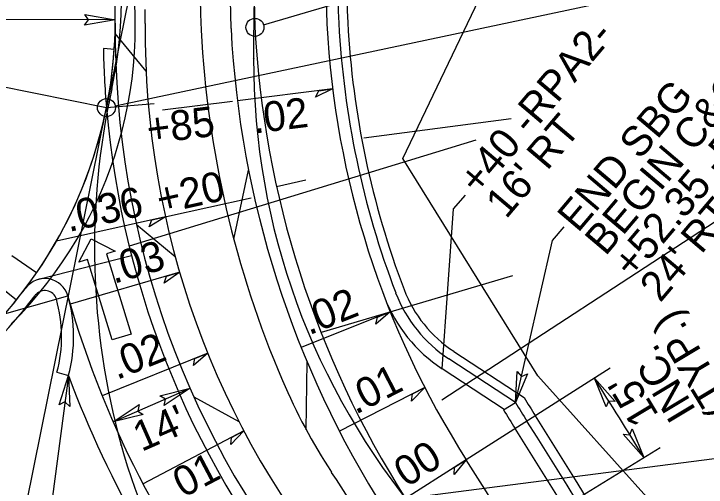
# Model space of a CAD drawing. Extents: x 1761082 to 1764358, y 421907 to 425434.
# Drawn here: x 1762765.1 to 1762880.6, y 423538.8 to 423617.8 of the extents above; entities that cross this region are included whole.
import ezdxf

# ---------------------------------------------------------------- set-up
doc = ezdxf.new("R2010")
doc.units = 0
for name, color, linetype in [('MARK HOOKS CENTER STRAIGHT LEFT TURN ARROW CELL', 7, 'Continuous'), ('MARK LEFT TURN ARROW CELL', 7, 'Continuous'), ('MARK STRAIGHT RIGHT ARROW CELL', 7, 'Continuous'), ('MARK UTURN ARROW CELL', 7, 'Continuous'), ('Prop Conc Shoulder Berm Gutter', 7, 'Continuous'), ('Prop Geotechnical Rock Plating', 7, 'Continuous'), ('Prop Horizontal Alignment Tick Large', 7, 'Continuous'), ('Prop Mkg 3ft Min Skp 3ft Wide White', 7, 'Continuous'), ('Prop Mkg 3ft Min Skp 9ft Wide White', 7, 'Continuous'), ('Prop Mkg Min Skp 6ft Yellow', 7, 'Continuous'), ('Prop Mkg Skp Wht', 7, 'Continuous'), ('Prop Mkg Solid White Diagonals', 7, 'Continuous'), ('Prop Mkg Solid White Edge Line', 7, 'Continuous'), ('Prop Mkg Solid White Lane Line', 7, 'Continuous'), ('Prop Mkg Solid White Multiple Diagonals V8i', 7, 'Continuous'), ('Prop Mkg Solid White Stop Bar', 7, 'Continuous'), ('Prop Mkg Solid White Wide Lane Line', 7, 'Continuous'), ('Prop Mkg Solid Yel Skip LT', 7, 'Continuous'), ('Prop Mkg Solid Yel Skip RT', 7, 'Continuous'), ('Prop Mkg Solid Yellow Diagonals', 7, 'Continuous'), ('Prop Mkg Solid Yellow Edge Line', 7, 'Continuous'), ('Prop Mkg Solid Yellow Lane Line', 7, 'Continuous'), ('Prop Mkr Yel 80ft Spc', 7, 'Continuous'), ('Scratch_Level_0', 7, 'Continuous'), ('Scratch_Level_1', 7, 'Continuous'), ('Scratch_Level_5', 7, 'Continuous')]:
    doc.layers.add(name, color=color, linetype=linetype)

msp = doc.modelspace()

# ---------------------------------------------------------------- linework, layer by layer
at = {"layer": 'MARK HOOKS CENTER STRAIGHT LEFT TURN ARROW CELL'}
for p, q in [((1762808.94, 423589.01), (1762813.82, 423590.09)), ((1762768.94, 423574.59), (1762764.82, 423577.42))]:
    msp.add_line(p, q, dxfattribs=at)
at = {"layer": 'MARK LEFT TURN ARROW CELL'}
for p, q in [((1762848.79, 423552.93), (1762837.68, 423560.24)), ((1762772.33, 423558), (1762774.26, 423557.48))]:
    msp.add_line(p, q, dxfattribs=at)
for centre, radius, start, end in [((1762902.22, 423620.56), 83, 139.7301, 182.9577), ((1762967.14, 423623.91), 148, 182.9577, 200.8339), ((1762707.06, 423616.97), 77, 302.5921, 323.1892), ((1762770.31, 423569.64), 2, 15.7844, 143.1892), ((1762850.31, 423579.46), 23, 200.8339, 236.6832), ((1762750.11, 423563.93), 23, 345.065, 15.7844)]:
    msp.add_arc(centre, radius, start, end, dxfattribs=at)
at = {"layer": 'MARK STRAIGHT RIGHT ARROW CELL'}
for centre, radius, start, end in [((1763313.22, 423228.23), 700, 137.52342, 147.0162), ((1762902.22, 423620.56), 97, 139.7301, 182.9577), ((1762967.14, 423623.91), 162, 182.9577, 212.4627)]:
    msp.add_arc(centre, radius, start, end, dxfattribs=at)
at = {"layer": 'MARK UTURN ARROW CELL'}
for points in [[(1762806.79, 423615.98), (1762960.53, 423661.22), (1763043.33, 423758.96)], [(1762782.05, 423602.47), (1762963.66, 423641.02), (1763045.54, 423737.66)], [(1762831.94, 423537.15), (1762958.32, 423553.44), (1763041.12, 423651.17)]]:
    msp.add_lwpolyline(points, dxfattribs=at)
for centre in [(1762805.35, 423615.56), (1762780.59, 423602.16), (1762780.59, 423602.16)]:
    msp.add_circle(centre, 1.5, dxfattribs=at)
at = {"layer": 'Prop Conc Shoulder Berm Gutter'}
msp.add_line((1762846.79, 423551.73), (1762848.79, 423552.93), dxfattribs=at)
for centre, radius, start, end in [((1762967.14, 423623.91), 138, 210.9558, 212.4627), ((1762097.24, 423070.52), 893, 19.5225, 32.46275)]:
    msp.add_arc(centre, radius, start, end, dxfattribs=at)
at = {"layer": 'Prop Geotechnical Rock Plating'}
for p, q in [((1762838.5, 423561.49), (1762850.22, 423553.78)), ((1762886.92, 423519.16), (1762852.54, 423557.42))]:
    msp.add_line(p, q, dxfattribs=at)
msp.add_lwpolyline([(1762852.54, 423557.42), (1762830, 423593.66), (1762847.81, 423630.88), (1762843.83, 423670.03)], dxfattribs=at)
for centre, radius, start, end in [((1762902.22, 423620.56), 81.5, 139.7301, 182.9577), ((1762967.14, 423623.91), 146.5, 182.9577, 200.8339), ((1762850.31, 423579.46), 21.5, 200.8339, 236.6832), ((1762967.14, 423623.91), 136.33, 210.9572, 212.4627), ((1762097.24, 423070.52), 894.67, 19.5239, 32.46275)]:
    msp.add_arc(centre, radius, start, end, dxfattribs=at)
at = {"layer": 'Prop Horizontal Alignment Tick Large'}
msp.add_line((1762780.59, 423602.16), (1762788.56, 423602.83), dxfattribs=at)
at = {"layer": 'Prop Mkg 3ft Min Skp 3ft Wide White'}
for centre, radius, start, end in [((1763313.22, 423228.23), 700, 137.52342, 147.0162), ((1762902.22, 423620.56), 97, 139.7301, 182.9577), ((1762707.06, 423616.97), 75, 348.6079, 38.8816), ((1762967.14, 423623.91), 162, 182.9577, 212.4627), ((1762707.06, 423616.97), 75, 249.1952, 348.6079), ((1762930.05, 423614.79), 150, 184.8317, 220.2713)]:
    msp.add_arc(centre, radius, start, end, dxfattribs=at)
at = {"layer": 'Prop Mkg 3ft Min Skp 9ft Wide White'}
msp.add_line((1762848.79, 423552.93), (1762837.68, 423560.24), dxfattribs=at)
for centre, radius, start, end in [((1762902.22, 423620.56), 83, 139.7301, 182.9577), ((1762967.14, 423623.91), 148, 182.9577, 200.8339), ((1762850.31, 423579.46), 23, 200.8339, 236.6832), ((1762967.14, 423623.91), 138, 210.9558, 212.4627), ((1762097.24, 423070.52), 893, 19.5225, 32.46275)]:
    msp.add_arc(centre, radius, start, end, dxfattribs=at)
at = {"layer": 'Prop Mkg Skp Wht'}
for centre, radius, start, end in [((1762902.22, 423620.56), 85, 139.7301, 182.9577), ((1762967.14, 423623.91), 150, 182.9577, 212.4627), ((1762707.06, 423616.97), 75, 302.5921, 324.7031), ((1762770.31, 423569.64), 4, 15.7844, 143.1892), ((1762930.05, 423614.79), 162, 195.7844, 220.2713), ((1762097.24, 423070.52), 881, 20.4405, 32.46275)]:
    msp.add_arc(centre, radius, start, end, dxfattribs=at)
at = {"layer": 'Prop Mkg Solid White Diagonals'}
for centre, radius, start, end in [((1762902.22, 423620.56), 106, 137.2008, 182.9577), ((1762707.06, 423616.97), 80, 359.4391, 1.1238), ((1762930.05, 423614.79), 143, 179.4404, 220.2713), ((1762967.14, 423623.91), 171, 182.9577, 203.1709), ((1762901.86, 423595.98), 100, 203.1709, 213.1463), ((1762097.24, 423070.52), 861, 30.06986, 33.14626)]:
    msp.add_arc(centre, radius, start, end, dxfattribs=at)
at = {"layer": 'Prop Mkg Solid White Edge Line'}
for start, end in [(348.6079, 38.8816), (249.1952, 348.6079)]:
    msp.add_arc((1762707.06, 423616.97), 75, start, end, dxfattribs=at)
at = {"layer": 'Prop Mkg Solid White Lane Line'}
for centre, radius, start, end in [((1762902.22, 423620.56), 106, 137.2008, 182.9577), ((1762707.06, 423616.97), 80, 359.4391, 1.1238), ((1762930.05, 423614.79), 143, 179.4404, 220.2713), ((1762967.14, 423623.91), 171, 182.9577, 203.1709), ((1762901.86, 423595.98), 100, 203.1709, 213.1463), ((1762097.24, 423070.52), 861, 30.06986, 33.14626)]:
    msp.add_arc(centre, radius, start, end, dxfattribs=at)
at = {"layer": 'Prop Mkg Solid White Multiple Diagonals V8i'}
for p, q in [((1762787.54, 423636.66), (1762780.59, 423602.16)), ((1762780.08, 423612.06), (1762781.9, 423611.93)), ((1762760.45, 423606.22), (1762780.59, 423602.16)), ((1762763.12, 423515.45), (1762780.59, 423602.16)), ((1762750.11, 423563.93), (1762774.16, 423570.73))]:
    msp.add_line(p, q, dxfattribs=at)
msp.add_arc((1762930.05, 423614.79), 150, 181.0456, 184.8317, dxfattribs=at)
at = {"layer": 'Prop Mkg Solid White Stop Bar'}
msp.add_line((1762846.89, 423551.79), (1762836.58, 423558.57), dxfattribs=at)
for centre, radius, start, end in [((1762750.11, 423563.93), 25, 345.065, 15.7844), ((1762850.31, 423579.46), 25, 200.8339, 236.6832), ((1762930.05, 423614.79), 166, 200.1967, 220.2713), ((1762967.14, 423623.91), 140.33, 210.9558, 212.4627), ((1762097.24, 423070.52), 890.67, 19.5225, 32.46275)]:
    msp.add_arc(centre, radius, start, end, dxfattribs=at)
at = {"layer": 'Prop Mkg Solid White Wide Lane Line'}
msp.add_line((1762648.54, 423663.87), (1762765.59, 423570.08), dxfattribs=at)
for centre, radius, start, end in [((1762705.65, 423613.56), 80, 12.8164, 194.1392), ((1762715.4, 423615.77), 70, 314.7787, 12.8164)]:
    msp.add_arc(centre, radius, start, end, dxfattribs=at)
at = {"layer": 'Prop Mkg Solid Yel Skip RT'}
for p, q in [((1762782.06, 423616.84), (1762632.07, 423617.11)), ((1762801.61, 423603.19), (1762789.93, 423601.73)), ((1762804.74, 423587.08), (1762790.59, 423583.95)), ((1762864.56, 423558.66), (1762840.58, 423543.4)), ((1762781.71, 423549.7), (1762794.53, 423555.33)), ((1762872.94, 423545.38), (1762850.76, 423531.8))]:
    msp.add_line(p, q, dxfattribs=at)
for points in [[(1762836.58, 423558.57), (1762838.48, 423585.27), (1762840.44, 423587.58)], [(1762848.79, 423552.93), (1762854.96, 423579.97), (1762856.9, 423582.26)], [(1762774.26, 423557.48), (1762764.26, 423481.75), (1762761.5, 423478.49)]]:
    msp.add_lwpolyline(points, dxfattribs=at)
msp.add_arc((1762097.24, 423070.52), 906.34, 31.47353, 32.46275, dxfattribs=at)
at = {"layer": 'Prop Mkg Solid Yellow Diagonals'}
for p, q in [((1762776, 423576.35), (1762778.04, 423580.27)), ((1762778.04, 423580.27), (1762782.02, 423578.2)), ((1762782.02, 423578.2), (1762780.59, 423577.76)), ((1762780.59, 423577.76), (1762784.71, 423564.38)), ((1762777.44, 423576.79), (1762776, 423576.35)), ((1762781.56, 423563.41), (1762777.44, 423576.79)), ((1762784.71, 423564.38), (1762781.56, 423563.41))]:
    msp.add_line(p, q, dxfattribs=at)
at = {"layer": 'Prop Mkg Solid Yellow Edge Line'}
msp.add_arc((1762707.06, 423616.97), 75, 324.7031, 359.4399, dxfattribs=at)
at = {"layer": 'Prop Mkg Solid Yellow Lane Line'}
for points in [[(1762776.96, 423617.72), (1762782.06, 423616.84), (1762776.93, 423615.94), (1762777.59, 423616.84)], [(1762850.78, 423557.71), (1762848.79, 423552.93), (1762849.05, 423558.13), (1762849.79, 423557.3)], [(1762772.72, 423552.54), (1762774.26, 423557.48), (1762774.49, 423552.28), (1762773.67, 423553.04)], [(1762863.91, 423552.21), (1762861.95, 423557), (1762865.44, 423553.13), (1762864.33, 423553.2)], [(1762789.5, 423554.08), (1762794.53, 423555.33), (1762790.19, 423552.44), (1762790.42, 423553.53)], [(1762786.73, 423550.95), (1762781.71, 423549.7), (1762786.04, 423552.6), (1762785.81, 423551.5)], [(1762868.26, 423548.56), (1762870.22, 423543.76), (1762866.73, 423547.64), (1762867.84, 423547.56)]]:
    msp.add_lwpolyline(points, close=True, dxfattribs=at)
at = {"layer": 'Prop Mkr Yel 80ft Spc'}
for centre in [(1762781.46, 423605.27), (1762781.46, 423605.27), (1762783.04, 423545.85), (1762783.04, 423545.85)]:
    msp.add_circle(centre, 0.0417, dxfattribs=at)
for centre, radius, start, end in [((1762713.08, 423620.24), 70, 347.6498, 41.9523), ((1762902.59, 423578.75), 124, 167.6498, 195.3842), ((1762879.45, 423572.38), 100, 195.3844, 229.878)]:
    msp.add_arc(centre, radius, start, end, dxfattribs=at)
at = {"layer": 'Scratch_Level_0'}
for p, q in [((1762787.2, 423608.25), (1762782.05, 423614.52)), ((1762801.81, 423580.23), (1762804.29, 423591.74)), ((1762792.07, 423577.27), (1762785.6, 423582.6)), ((1762769.32, 423573.51), (1762784.77, 423577.48)), ((1762813.91, 423548.4), (1762814.04, 423559.74)), ((1762802.73, 423549.71), (1762795.19, 423553.84))]:
    msp.add_line(p, q, dxfattribs=at)
for centre, radius, start, end in [((1762902.22, 423620.56), 101, 139.7301, 182.9577), ((1762707.06, 423616.97), 75, 359.4399, 1.123), ((1762930.05, 423614.79), 148, 179.4399, 220.2713), ((1762967.14, 423623.91), 166, 182.9577, 212.4627)]:
    msp.add_arc(centre, radius, start, end, dxfattribs=at)
at = {"layer": 'Scratch_Level_1'}
for p, q in [((1762932.82, 423616.24), (1762836.54, 423553.36)), ((1762848.05, 423600.31), (1762823.49, 423597.09)), ((1762848.29, 423574.07), (1762816.38, 423564.61))]:
    msp.add_line(p, q, dxfattribs=at)
msp.add_lwpolyline([(1762842.16, 423596.74), (1762784.37, 423579.06)], dxfattribs=at)
for centre in [(1762805.11, 423610.4), (1762805.11, 423610.4), (1762781.46, 423605.27), (1762781.46, 423605.27), (1762783.04, 423545.85), (1762783.04, 423545.85)]:
    msp.add_circle(centre, 0.0417, dxfattribs=at)
for centre, radius, start, end in [((1762713.08, 423620.24), 70, 347.6498, 41.9523), ((1763305.11, 423609.67), 500, 176.4538, 179.9158), ((1762923.61, 423610.23), 118.5, 179.9158, 220.1525), ((1762902.59, 423578.75), 124, 167.6498, 195.3842), ((1762879.45, 423572.38), 100, 195.3844, 229.878)]:
    msp.add_arc(centre, radius, start, end, dxfattribs=at)
at = {"layer": 'Scratch_Level_5'}
for p, q in [((1762818.3, 423605.28), (1762802.42, 423603.29)), ((1762790.43, 423583.91), (1762772.26, 423579.89)), ((1762792.8, 423574.68), (1762774.56, 423569.35)), ((1762827.92, 423568.08), (1762813.07, 423562.12)), ((1762797.49, 423561.18), (1762779.87, 423554.05)), ((1762833.68, 423555.45), (1762819.44, 423548.14)), ((1762803.5, 423548.21), (1762786.69, 423539.36)), ((1762840.58, 423543.4), (1762827.08, 423534.81))]:
    msp.add_line(p, q, dxfattribs=at)
for points in [[(1762818.3, 423605.28), (1762815.45, 423603.91), (1762816, 423604.99)], [(1762790.43, 423583.91), (1762787.72, 423582.29), (1762788.17, 423583.41)], [(1762792.8, 423574.68), (1762790.2, 423572.88), (1762790.58, 423574.03)], [(1762827.92, 423568.08), (1762825.5, 423566.03), (1762825.77, 423567.22)], [(1762797.49, 423561.18), (1762795.08, 423559.13), (1762795.34, 423560.31)], [(1762833.68, 423555.45), (1762831.46, 423553.19), (1762831.62, 423554.39)], [(1762803.5, 423548.21), (1762801.31, 423545.93), (1762801.45, 423547.13)], [(1762840.58, 423543.4), (1762838.58, 423540.95), (1762838.62, 423542.16)]]:
    msp.add_lwpolyline(points, close=True, dxfattribs=at)

# ---------------------------------------------------------------- texts
at = {"layer": 'Prop Mkg Min Skp 6ft Yellow'}
for s, rotation, p in [('.02', 7.1371, (1762805.24, 423597.82)), ('.036', 12.4711, (1762774.3, 423581.39)), ('.03', 16.2909, (1762781.8, 423572.73)), ('.02', 21.8536, (1762814.37, 423564.14)), ('(TYP.)', 120.979, (1762885.45, 423552.28)), ('.02', 22.0204, (1762782.32, 423556.68)), ('INC.', 120.979, (1762879.02, 423551.64)), ('.01', 27.1588, (1762822.13, 423550.88)), ("15' ", 120.979, (1762872.78, 423550.87)), ('00', 32.4627, (1762830.62, 423538.68)), ('.01', 27.75, (1762791.73, 423536.1))]:
    msp.add_text(s, height=5, rotation=rotation, dxfattribs=at).set_placement(p)
at = {"layer": 'Prop Mkg Solid Yel Skip LT'}
for s, rotation, p in [('+40 -RPA2-', 49.7301, (1762842.66, 423587.33)), ('BEGIN C&G', 49.7301, (1762863.79, 423577.26)), ('+52.35 -RPA2-', 49.7301, (1762868.37, 423573.38)), ('END SBG', 49.7301, (1762859.21, 423581.14)), ('+85', 7.1371, (1762787.61, 423596.07)), ("16' RT", 49.7301, (1762847.24, 423583.45)), ('+20', 12.4711, (1762789.55, 423584.35)), ("24' RT", 49.7301, (1762872.94, 423569.5)), ("14'", 23.6904, (1762786.43, 423544.68))]:
    msp.add_text(s, height=5, rotation=rotation, dxfattribs=at).set_placement(p)

doc.saveas('drawing.dxf')
